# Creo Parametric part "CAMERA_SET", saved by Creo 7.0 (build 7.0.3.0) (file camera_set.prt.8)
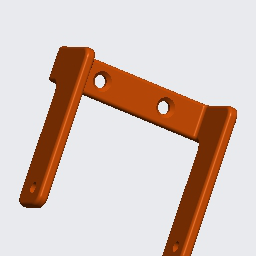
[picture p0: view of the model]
Units: millimeter Kilogram Sec (mmKs); MM, KILOGRAM, SECS

Created from: XX_SOLID_PART_MMKS_ABS.PRT

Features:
  1. coordinate system
  2. datum plane "RIGHT"
  3. datum plane "TOP"
  4. datum plane "FRONT"
  5. extrusion "Extrude 1"
  6. extrusion "Extrude 2"
  7. extruded cut "Extrude 3"
  8. extruded cut "Extrude 4"
  9. extruded cut "Extrude 5"
  10. round "Round 1"
  11. round "Round 2"
  12. chamfer "Chamfer 1"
